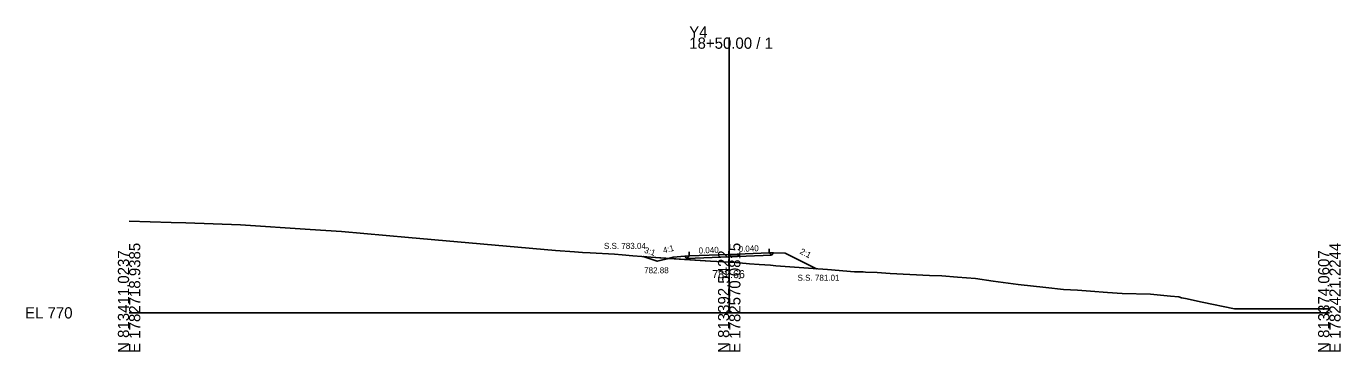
# Model space of a CAD drawing. Extents: x -26 to 3903, y -10 to 9562.
# Drawn here: x 974.3 to 1302.8, y 490.3 to 571.5 of the extents above; entities that cross this region are included whole.
import ezdxf

# ---------------------------------------------------------------- set-up
doc = ezdxf.new("R2010")
doc.units = 0
for name, color, linetype in [('Exist Cross Section Cell', 7, 'Continuous'), ('Exist XS Center Line Elevation Label', 7, 'Continuous'), ('Exist XS Ground Line', 7, 'Continuous'), ('Prop XS Ditch Slope Text', 7, 'Continuous'), ('Prop XS Ditch Standard Text', 7, 'Continuous'), ('Prop XS Dump Level', 7, 'Continuous'), ('Prop XS Earthwork Shape', 7, 'Continuous'), ('Prop XS EOT Tick Mark', 7, 'Continuous'), ('Prop XS Finish Grade', 7, 'Continuous'), ('Prop XS Finish Grade Earthwork', 7, 'Continuous'), ('Prop XS Finish Grade Pavement', 7, 'Continuous'), ('Prop XS Pvmt Edge Slope', 7, 'Continuous'), ('Prop XS SE Text', 7, 'Continuous'), ('Prop XS Side Slope Text', 7, 'Continuous'), ('Prop XS SS Elevation Text', 7, 'Continuous'), ('Prop XS Subgrade Earthwork', 7, 'Continuous')]:
    doc.layers.add(name, color=color, linetype=linetype)

msp = doc.modelspace()

# ---------------------------------------------------------------- linework, layer by layer
at = {"layer": 'Exist Cross Section Cell'}
for p, q in [((1150, 500), (1150, 568.73)), ((1000, 500), (1150, 500)), ((1150, 500), (1300, 500))]:
    msp.add_line(p, q, dxfattribs=at)
at = {"layer": 'Exist XS Ground Line'}
for p, q in [((1000, 522.91), (1010.51, 522.59)), ((1010.51, 522.59), (1014.22, 522.45)), ((1014.22, 522.45), (1027.84, 522)), ((1027.84, 522), (1045.27, 520.82)), ((1045.27, 520.82), (1053.08, 520.32)), ((1053.08, 520.32), (1069.84, 518.77)), ((1069.84, 518.77), (1106.54, 515.59)), ((1106.54, 515.59), (1111.29, 515.26)), ((1111.29, 515.26), (1113.29, 515.09)), ((1113.29, 515.09), (1115.23, 514.99)), ((1115.23, 514.99), (1121.29, 514.66)), ((1121.29, 514.66), (1123.21, 514.45)), ((1123.21, 514.45), (1125.88, 514.23)), ((1125.88, 514.23), (1130.37, 513.9)), ((1130.37, 513.9), (1145.3, 512.9)), ((1145.3, 512.9), (1150, 512.66)), ((1150, 512.66), (1150.76, 512.62)), ((1150.76, 512.62), (1155.09, 512.22)), ((1155.09, 512.22), (1157.46, 512.05)), ((1157.46, 512.05), (1160.35, 511.88)), ((1160.35, 511.88), (1160.97, 511.81)), ((1160.97, 511.81), (1161.67, 511.76)), ((1161.67, 511.76), (1170.99, 511.06)), ((1170.99, 511.06), (1174.55, 510.84)), ((1174.55, 510.84), (1181.34, 510.22)), ((1181.34, 510.22), (1183.09, 510.22)), ((1183.09, 510.22), (1183.49, 510.21)), ((1183.49, 510.21), (1184.06, 510.19)), ((1184.06, 510.19), (1187.01, 510.04)), ((1187.01, 510.04), (1190.22, 509.85)), ((1190.22, 509.85), (1200.1, 509.34)), ((1200.1, 509.34), (1203.16, 509.2)), ((1203.16, 509.2), (1207.06, 508.92)), ((1207.06, 508.92), (1211.53, 508.55)), ((1211.53, 508.55), (1216, 507.95)), ((1216, 507.95), (1222.25, 507.08)), ((1222.25, 507.08), (1229.1, 506.34)), ((1229.1, 506.34), (1233.55, 505.81)), ((1233.55, 505.81), (1237.03, 505.64)), ((1237.03, 505.64), (1238.13, 505.61)), ((1238.13, 505.61), (1240.32, 505.42)), ((1240.32, 505.42), (1244.55, 505.08)), ((1244.55, 505.08), (1248.24, 504.87)), ((1248.24, 504.87), (1255.3, 504.63)), ((1255.3, 504.63), (1260.27, 504.15)), ((1260.27, 504.15), (1262.37, 503.98)), ((1262.37, 503.98), (1263.08, 503.77)), ((1263.08, 503.77), (1264.05, 503.57)), ((1264.05, 503.57), (1268.22, 502.66)), ((1268.22, 502.66), (1276.28, 501.03)), ((1276.28, 501.03), (1277.32, 501.03)), ((1277.32, 501.03), (1278.16, 501.03)), ((1278.16, 501.03), (1283.99, 501.03)), ((1283.99, 501.03), (1284.65, 501.03)), ((1284.65, 501.03), (1287.34, 501.03)), ((1287.34, 501.03), (1300, 501.03))]:
    msp.add_line(p, q, dxfattribs=at)
at = {"layer": 'Prop XS Dump Level'}
for p, q in [((1140, 514.2), (1150, 514.6)), ((1150, 514.6), (1160, 515))]:
    msp.add_line(p, q, dxfattribs=at)
at = {"layer": 'Prop XS Earthwork Shape'}
for points in [[(1130.37, 513.9), (1134.88, 513.6), (1132, 512.88), (1128.53, 514.04)], [(1136, 513.88), (1134.88, 513.6), (1145.3, 512.9), (1150, 512.66), (1150.76, 512.62), (1155.09, 512.22), (1157.46, 512.05), (1160.35, 511.88), (1160.97, 511.81), (1161.67, 511.76), (1170.99, 511.06), (1171.83, 511.01), (1164, 514.92), (1161.1, 514.98), (1160.56, 514.44), (1150.02, 514.02), (1139.39, 513.59), (1138.87, 514.11)]]:
    msp.add_lwpolyline(points, close=True, dxfattribs=at)
at = {"layer": 'Prop XS EOT Tick Mark'}
for p, q in [((1160, 515), (1160, 516)), ((1140, 514.2), (1140, 515.2))]:
    msp.add_line(p, q, dxfattribs=at)
at = {"layer": 'Prop XS Finish Grade'}
for p, q in [((1140, 514.2), (1138.87, 514.11)), ((1160, 515), (1161.1, 514.98))]:
    msp.add_line(p, q, dxfattribs=at)
at = {"layer": 'Prop XS Finish Grade Earthwork'}
for p, q in [((1132, 512.88), (1128.53, 514.04)), ((1136, 513.88), (1132, 512.88)), ((1138.87, 514.11), (1136, 513.88)), ((1161.1, 514.98), (1164, 514.92)), ((1164, 514.92), (1171.83, 511.01))]:
    msp.add_line(p, q, dxfattribs=at)
at = {"layer": 'Prop XS Finish Grade Pavement'}
for p, q in [((1140, 514.2), (1150, 514.6)), ((1150, 514.6), (1160, 515))]:
    msp.add_line(p, q, dxfattribs=at)
at = {"layer": 'Prop XS Pvmt Edge Slope'}
for p, q in [((1140, 514.2), (1139.39, 513.59)), ((1160, 515), (1160.56, 514.44))]:
    msp.add_line(p, q, dxfattribs=at)
at = {"layer": 'Prop XS Subgrade Earthwork'}
for p, q in [((1139.39, 513.59), (1138.87, 514.11)), ((1139.39, 513.59), (1150.02, 514.02)), ((1150.02, 514.02), (1160.56, 514.44)), ((1160.56, 514.44), (1161.1, 514.98))]:
    msp.add_line(p, q, dxfattribs=at)

# ---------------------------------------------------------------- texts
at = {"layer": 'Exist Cross Section Cell'}
for s, p in [('Y4', (1140, 568.73)), ('18+50.00 / 1', (1140, 565.93)), ('EL 770', (974, 498.6))]:
    msp.add_text(s, height=2.8, dxfattribs=at).set_placement(p)
for s, p in [('E 1782718.9385', (1002.8, 490)), ('E 1782570.0815', (1152.8, 490)), ('E 1782421.2244', (1302.8, 490)), ('N 813411.0237', (1000, 490)), ('N 813392.5422', (1150, 490)), ('N 813374.0607', (1300, 490))]:
    msp.add_text(s, height=2.8, rotation=90, dxfattribs=at).set_placement(p)
at = {"layer": 'Exist XS Center Line Elevation Label'}
msp.add_text('782.66', height=2, dxfattribs=at).set_placement((1145.73, 508.66))
at = {"layer": 'Prop XS Ditch Slope Text'}
msp.add_text('4:1', height=1.5, rotation=14.0362, dxfattribs=at).set_placement((1133.64, 514.84))
at = {"layer": 'Prop XS Ditch Standard Text'}
msp.add_text('782.88', height=1.5, dxfattribs=at).set_placement((1128.74, 509.88))
at = {"layer": 'Prop XS Dump Level'}
for p in [(1136, 513.84), (1164, 514.88)]:
    msp.add_text('Case1', height=0.04, dxfattribs=at).set_placement(p)
at = {"layer": 'Prop XS SE Text'}
for p in [(1142.38, 514.8), (1152.38, 515.2)]:
    msp.add_text('0.040', height=1.5, rotation=2.2906, dxfattribs=at).set_placement(p)
at = {"layer": 'Prop XS Side Slope Text'}
for s, rotation, p in [('3:1', 342.2871, (1128.63, 515.04)), ('2:1', 333.4349, (1167.5, 514.85))]:
    msp.add_text(s, height=1.5, rotation=rotation, dxfattribs=at).set_placement(p)
at = {"layer": 'Prop XS SS Elevation Text'}
for s, p in [('S.S. 783.04', (1118.69, 515.97)), ('S.S. 781.01', (1167.08, 508.01))]:
    msp.add_text(s, height=1.5, dxfattribs=at).set_placement(p)

doc.saveas('drawing.dxf')
